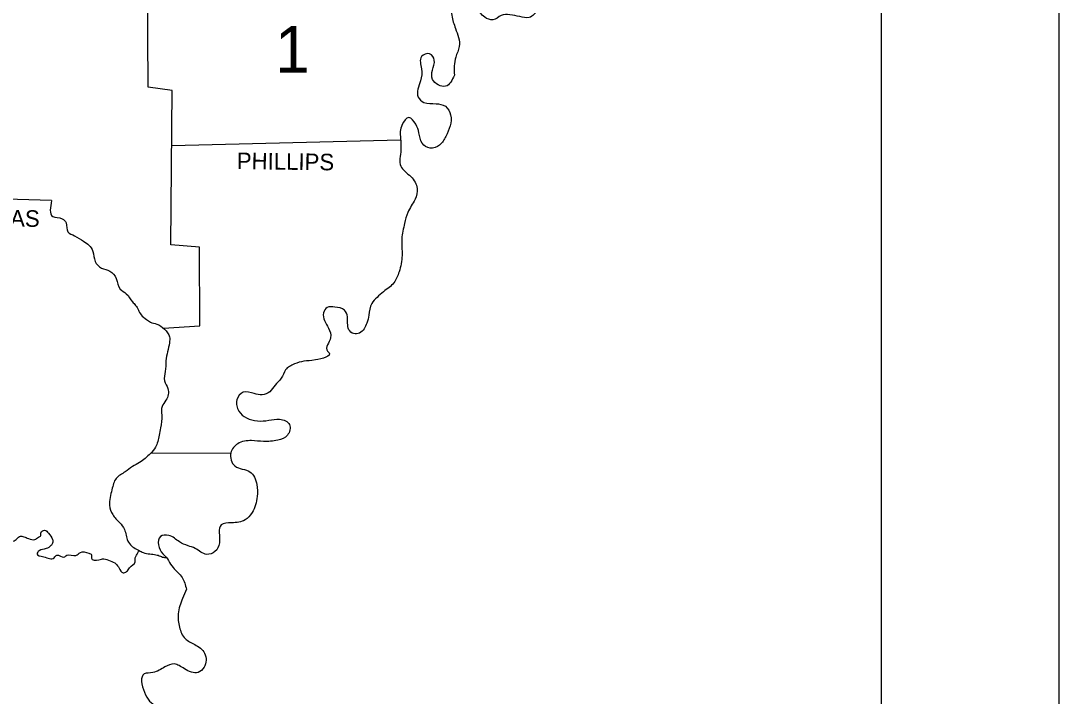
# Model space of a CAD drawing. Extents: x 840176 to 859715, y 1589036 to 1600368.
# Drawn here: x 855714 to 857176, y 1596633 to 1597585 of the extents above; entities that cross this region are included whole.
import ezdxf

# ---------------------------------------------------------------- set-up
doc = ezdxf.new("R2010")
doc.units = 0
doc.layers.add('DSN_DRFT_Border', color=7, linetype='Continuous')
doc.layers.add('SHET_Border-Text', color=7, linetype='Continuous')

msp = doc.modelspace()

# ---------------------------------------------------------------- linework, layer by layer
at = {"layer": 'DSN_DRFT_Border'}
for p, q in [((855896.6, 1596975.8), (856009.4, 1596976.4)), ((855896.6, 1596975.8), (856009.4, 1596976.4)), ((855916, 1596828.9), (855917.7, 1596828.9))]:
    msp.add_line(p, q, dxfattribs=at)
msp.add_lwpolyline([(840175.5, 1600035.6), (840175.5, 1589035.6), (857175.5, 1589035.6), (857175.5, 1600035.6)], close=True, dxfattribs=at)
for points in [[(855914.3, 1597152), (855965.5, 1597155.4), (855965.2, 1597266.2), (855924.7, 1597269.3), (855926.9, 1597486.5), (855892.7, 1597491.5), (855891.8, 1597637.8), (856361, 1597640.9)], [(855926.1, 1597409.3), (856248.2, 1597417.1)], [(855757, 1597331.8), (855549.7, 1597337.7), (855548.5, 1597270.2), (855129.6, 1597268.7)]]:
    msp.add_lwpolyline(points, dxfattribs=at)
for points in [[(856562.1, 1598051), (856564.3, 1598035.5), (856554.6, 1598018.4), (856551.2, 1598001.6), (856553.1, 1597984.4), (856535.6, 1597975.1), (856520.1, 1597963.9), (856529.1, 1597951.1), (856545.3, 1597938.7), (856561.8, 1597929.7), (856572.1, 1597920), (856575.2, 1597897.9), (856578, 1597883.3), (856583.3, 1597864), (856585.4, 1597850), (856575.8, 1597833.8), (856564.3, 1597830.4), (856551.8, 1597834.4), (856537.5, 1597835.4), (856526, 1597824.2), (856517.9, 1597809.2), (856509.8, 1597793.7), (856503.6, 1597780.6), (856497.7, 1597766.6), (856485.5, 1597750.1), (856470.9, 1597747.3), (856453.2, 1597742.9), (856442.9, 1597730.8), (856444.5, 1597710.6), (856454.4, 1597696.6), (856462.2, 1597679.8), (856467.8, 1597664.8), (856464.7, 1597646.5), (856457.2, 1597632.8), (856447.6, 1597624.4), (856442.9, 1597606.9), (856436.1, 1597593.9), (856429.2, 1597589.5), (856416.1, 1597590.8), (856402.1, 1597593.3), (856390, 1597592.3), (856378.2, 1597586.1), (856366.7, 1597590.1), (856354.8, 1597602.9), (856345.2, 1597612.9), (856334, 1597616.6), (856322.5, 1597610.7), (856320.3, 1597592.6), (856325.6, 1597574), (856330.9, 1597548.7), (856325.9, 1597533.8), (856324, 1597508.3)], [(856324, 1597508.3), (856311.6, 1597492.7), (856293.2, 1597502.4), (856293.2, 1597515.4), (856295.7, 1597529.5), (856289.2, 1597538.2), (856277.7, 1597534.4), (856277.7, 1597517.3), (856276.4, 1597500.5), (856273, 1597477.5), (856281.1, 1597470), (856298.2, 1597468.1), (856311.3, 1597464.4), (856318.7, 1597452.3), (856318.1, 1597436.7), (856311.9, 1597422.1), (856303.2, 1597409.9), (856289.8, 1597405.6), (856278.6, 1597412.4), (856274.2, 1597427.1), (856269.6, 1597439.2), (856259.9, 1597448.5), (856250.3, 1597438.6), (856248.1, 1597419.3), (856248.7, 1597402.8), (856248.4, 1597380.1), (856262.7, 1597365.4), (856271.7, 1597348.6), (856268.6, 1597333.4), (856258.4, 1597315), (856254, 1597299.5), (856250, 1597277.7), (856250.3, 1597254.3), (856246.2, 1597231.3), (856238.8, 1597215.8), (856224.4, 1597203.3), (856215.1, 1597195.2), (856207.6, 1597186.8), (856203.6, 1597170.3), (856200.8, 1597159.1), (856190.5, 1597145.1), (856182.1, 1597144.2), (856175.6, 1597149.8), (856173.7, 1597159.1), (856173.4, 1597168.1), (856169.4, 1597177.5), (856155.7, 1597181.5), (856144.8, 1597181.2), (856139.8, 1597173.4), (856146.6, 1597152), (856149.7, 1597138.3), (856145.4, 1597119.6), (856147.6, 1597117.4), (856128.3, 1597107.1), (856112.1, 1597105.3), (856099, 1597101.5), (856086.3, 1597093.1), (856080.3, 1597081.3), (856071.6, 1597071.7), (856064.2, 1597062.3), (856053.6, 1597058), (856042.1, 1597059.8), (856026.8, 1597061.7), (856017.8, 1597050.8), (856020.6, 1597034.9), (856031.2, 1597025.6), (856046.7, 1597021.2), (856062.6, 1597022.2), (856077.9, 1597023.7), (856091.9, 1597016), (856089.1, 1597001.3), (856075.4, 1596994.2), (856055.1, 1596992.3), (856038.6, 1596993.5), (856019, 1596989.2), (856009.4, 1596976.4), (856015, 1596957.8), (856036.2, 1596949.7), (856045.8, 1596931.6), (856046.4, 1596914.8), (856039.3, 1596892.1), (856029.3, 1596881.8), (856010.3, 1596877.8), (855995.7, 1596874.7), (855993.2, 1596849.5), (855987, 1596837.3), (855975.5, 1596833.3), (855959, 1596841.7), (855949, 1596845.4), (855936.9, 1596851), (855921.9, 1596860), (855910.1, 1596858.5), (855913.5, 1596834.2), (855914.5, 1596833.3), (855927.9, 1596814.9), (855940.6, 1596800.9), (855946.8, 1596784.1)], [(855757, 1597331.8), (855758.6, 1597309.4), (855771.8, 1597306.1), (855777.3, 1597300.1), (855780, 1597287.5), (855789.3, 1597282), (855801.9, 1597274.3), (855809.6, 1597268.9), (855815, 1597260.1), (855818.3, 1597245.9), (855827.1, 1597236.5), (855839.1, 1597232.2), (855847.9, 1597221.8), (855853.4, 1597207), (855862.1, 1597200.4), (855870.9, 1597188.9), (855875.3, 1597184), (855883, 1597170.8), (855890.6, 1597164.2), (855896.1, 1597160.4), (855904.9, 1597157.7), (855915.8, 1597150.6), (855922.9, 1597139.6), (855922.9, 1597131.4), (855920.2, 1597118.8), (855918, 1597105.7), (855916.9, 1597090.9), (855915.8, 1597077.7), (855920.7, 1597066.8), (855918, 1597050.3), (855912.5, 1597041.6), (855912, 1597029.5), (855910.3, 1597011.5), (855908.2, 1597001), (855903.2, 1596984.1), (855896.6, 1596975.8)], [(855757, 1597331.8), (855758.6, 1597309.4), (855771.8, 1597306.1), (855777.3, 1597300.1), (855780, 1597287.5), (855789.3, 1597282), (855801.9, 1597274.3), (855809.6, 1597268.9), (855815, 1597260.1), (855818.3, 1597245.9), (855827.1, 1597236.5), (855839.1, 1597232.2), (855847.9, 1597221.8), (855853.4, 1597207), (855862.1, 1597200.4), (855870.9, 1597188.9), (855875.3, 1597184), (855883, 1597170.8), (855890.6, 1597164.2), (855896.1, 1597160.4), (855904.9, 1597157.7), (855915.8, 1597150.6), (855922.9, 1597139.6), (855922.9, 1597131.4), (855920.2, 1597118.8), (855918, 1597105.7), (855916.9, 1597090.9), (855915.8, 1597077.7), (855920.7, 1597066.8), (855918, 1597050.3), (855912.5, 1597041.6), (855912, 1597029.5), (855910.3, 1597011.5), (855908.2, 1597001), (855903.2, 1596984.1), (855896.1, 1596975.3)], [(855548.5, 1597048.9), (855557.2, 1597043.3), (855568.7, 1597044), (855575.9, 1597047.1), (855582.4, 1597046.8), (855590.2, 1597041.8), (855596.1, 1597035.6), (855599.8, 1597030.6), (855602.3, 1597022.5), (855602.3, 1597015.6), (855605.1, 1597005.7), (855608.6, 1597001.6), (855612.6, 1596994.8), (855615.7, 1596987.9), (855617, 1596983.9), (855623.2, 1596976.4), (855628.8, 1596977.4), (855633.4, 1596976.4), (855640.3, 1596972.7), (855649.9, 1596965.2), (855651.8, 1596962.7), (855658, 1596948.7), (855659.3, 1596940), (855660.2, 1596928.5), (855662.4, 1596917.6), (855667.1, 1596905.5), (855669.2, 1596897.4), (855674.2, 1596885.9), (855677.6, 1596878.1), (855682, 1596868.4), (855688.2, 1596857.2), (855691.3, 1596850.7), (855700.7, 1596851.3), (855706.9, 1596854.1), (855711.9, 1596858.5), (855718.1, 1596857.9), (855724.3, 1596855.7), (855733.3, 1596854.1), (855738.6, 1596857.5), (855741.7, 1596859.7), (855742.1, 1596864.4), (855747, 1596867.2), (855752.6, 1596863.1), (855758.2, 1596854.4), (855758.2, 1596849.1), (855756.1, 1596845.7), (855749.2, 1596841.4), (855739.3, 1596838.3), (855736.5, 1596834.2), (855745.8, 1596829.8), (855760.4, 1596828.6), (855764.5, 1596832.3), (855774.4, 1596829.5), (855778.2, 1596832), (855791.2, 1596831.7), (855797.5, 1596836.1), (855809.3, 1596835.1), (855813, 1596832.7), (855813, 1596828), (855823.3, 1596825.5), (855830.4, 1596827), (855839.5, 1596824.2), (855847.6, 1596819.9), (855851.9, 1596814), (855857.5, 1596807.4), (855862.5, 1596809), (855866.5, 1596814.3), (855874.6, 1596823), (855874.6, 1596828.3), (855876.5, 1596832), (855880.2, 1596838.9)], [(855896.1, 1596975.3), (855880.8, 1596962.7), (855870.9, 1596957.2), (855860.5, 1596949.6), (855847.9, 1596940.3), (855841.9, 1596924.4), (855838.6, 1596902.5), (855843, 1596889.3), (855852.8, 1596877.8), (855859.4, 1596868.5), (855864.3, 1596852.1), (855876.4, 1596840.6), (855880.2, 1596838.9)], [(855880.2, 1596838.9), (855885.8, 1596835.8), (855895.2, 1596833.9), (855903.9, 1596832.7), (855910.1, 1596830.8), (855912.9, 1596829.5), (855916, 1596828.9)], [(855946.8, 1596784.1), (855941.2, 1596771.3), (855935.3, 1596749.6), (855936.9, 1596730.9), (855945, 1596714.7), (855958.4, 1596706.3), (855972.4, 1596693.9), (855971.7, 1596674.2), (855963.3, 1596667.1), (855944, 1596672.1), (855929.4, 1596678.9), (855916.6, 1596674.9), (855899.5, 1596666.8), (855887.4, 1596664.9), (855887.7, 1596639.1), (855904.5, 1596620.1), (855919.4, 1596620.1), (855936.6, 1596618.2), (855942.5, 1596598.3), (855932.5, 1596582.1), (855916, 1596573.4), (855895.5, 1596583.4), (855880.9, 1596594), (855865.6, 1596603.9), (855847.2, 1596608.9), (855836.7, 1596606.7), (855832, 1596583.7), (855840.7, 1596562.8), (855855, 1596548.2), (855868.1, 1596529.8), (855865.9, 1596516.1), (855856, 1596512.4), (855838.5, 1596508.7), (855828, 1596502.8), (855825.5, 1596498.7), (855830.8, 1596480), (855835.7, 1596459.5), (855835.7, 1596444.3), (855829.8, 1596429.9), (855820.5, 1596408.2), (855821.4, 1596394.2), (855828, 1596387.3), (855836.4, 1596389.8), (855847.2, 1596397.3), (855854.1, 1596406.3), (855860.3, 1596416.9), (855871.8, 1596426.2), (855885.8, 1596418.1), (855889.6, 1596401.3), (855881.2, 1596386.4), (855869.7, 1596379.8), (855855.7, 1596374.5), (855844.8, 1596362.4), (855847.6, 1596348.1), (855856, 1596340.6), (855876.2, 1596344), (855889.9, 1596350), (855897.4, 1596358.1), (855906.7, 1596367.4), (855911.7, 1596376.4), (855918.8, 1596386.4), (855931.6, 1596389.2), (855937.5, 1596380.8), (855935.3, 1596362.4), (855927.5, 1596345), (855917.3, 1596329.7), (855905.8, 1596319.5), (855891.8, 1596297.1), (855894.6, 1596276.2), (855899.5, 1596259.1), (855907.3, 1596246), (855920.4, 1596248.8), (855935.3, 1596250.7), (855944.3, 1596243.5), (855943.1, 1596228.3), (855931.9, 1596213.3), (855921.9, 1596199.3), (855916.3, 1596179.1), (855918.5, 1596165.4), (855918.5, 1596153), (855913.8, 1596139.3), (855906.1, 1596131.5), (855886.2, 1596132.4), (855865, 1596134.6), (855853.2, 1596128.1), (855855.3, 1596109.1), (855868.1, 1596095.7), (855876.8, 1596088.5), (855889.3, 1596073), (855894.9, 1596060.5), (855893, 1596049.6), (855885.5, 1596040.3), (855863.1, 1596029.1)]]:
    msp.add_spline(points, degree=3, dxfattribs=at)
at = {"layer": 'SHET_Border-Text'}
for points in [[(840175.5, 1589035.6), (857175.5, 1589035.6), (857175.5, 1600035.6), (840175.5, 1600035.6)], [(840425.5, 1589285.6), (856925.5, 1589285.6), (856925.5, 1599785.6), (840425.5, 1599785.6)]]:
    msp.add_lwpolyline(points, close=True, dxfattribs=at)

# ---------------------------------------------------------------- texts
at = {"layer": 'DSN_DRFT_Border'}
msp.add_text('1', height=65.7, dxfattribs=at).set_placement((856071.6, 1597511.9))
for s, rotation, p in [('PHILLIPS', 359.217, (856017.6, 1597376)), ('ARKANSAS', 359.2655, (855570.1, 1597296.7))]:
    msp.add_text(s, height=23.34, rotation=rotation, dxfattribs=at).set_placement(p)

doc.saveas('drawing.dxf')
